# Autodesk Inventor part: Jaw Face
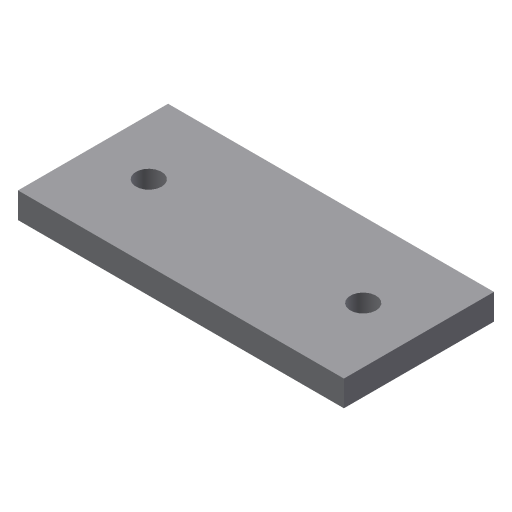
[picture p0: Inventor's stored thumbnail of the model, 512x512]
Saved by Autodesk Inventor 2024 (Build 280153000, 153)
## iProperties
Shininess: 77.0
Length Units: 11269
Angle Units: 11279
Time Units: 11290
Mass Units: 11283
Length Display Precision: 3
Angle Display Precision: 2
Compacted: True
Created: 2002-02
Part Number: Jaw Face
Document SubType Name: Modeling
Designer: ***
Density: 1 g/cm^3
Material: Generic
Appearance: Default
Density: 0.0
Volumn: 0.0
Area: 0.0
PropertySet Name: Model Information
Control State: 0
Master: False
Checked Out: False
Author: ***
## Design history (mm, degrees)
sketch "Sketch1"
  geometry: L1 (-79.661, -8.43)-(-3.661, -8.43); L2 (-3.661, -8.43)-(-3.661, -43.43); L3 (-3.661, -43.43)-(-79.661, -43.43); L4 (-79.661, -43.43)-(-79.661, -8.43); C1 r 3 at (-66.661, -25.93); C2 r 3 at (-16.661, -25.93)
  constraints: 8 end point, 2 centre point, 2 parallel, 1 equal radius, 1 horizontal, 1 perpendicular
  dimensions: "d0" = 76 distance of L2.end L3.end; "d1" = 6 diameter of C1; "d2" = 50 distance of C2.centre C1.centre; "d3" = 35 distance of L1.end L2.end; "d4" = 17.5 distance from line of L3 C2.centre; "d5" = 13 distance from line of L2 C2.centre; "d6" = 13 distance from line of L4 C1.centre
extrude "Extrusion1" new body sketch "Sketch1" stored distance "d7" = 6; taper "d8" = 0 deg
body "Solid1"
